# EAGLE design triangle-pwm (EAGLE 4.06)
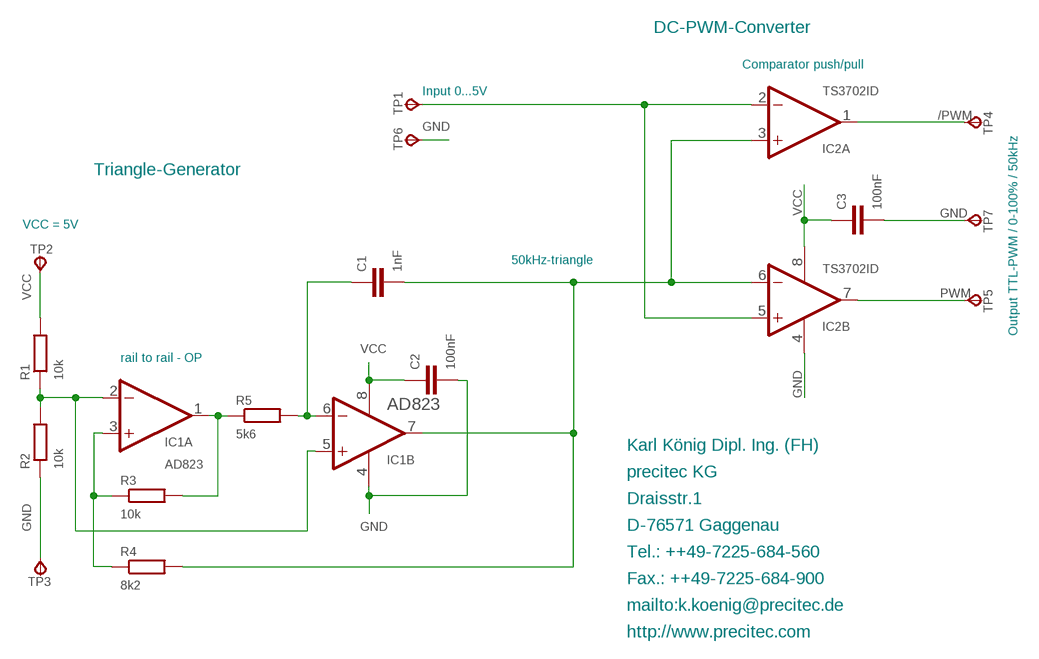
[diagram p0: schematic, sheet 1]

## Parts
C1  1nF  C-EUC1206  [C1206]
C2  100nF  C-EUC1206  [C1206]
C3  100nF  C-EUC1206  [C1206]
IC1  AD823  2AMP_P8+4D  [SO08]
IC2  TS3702ID  2AMP_P8+4D  [SO08]
R1  10k  R-EU_R1206  [R1206]
R2  10k  R-EU_R1206  [R1206]
R3  10k  R-EU_R1206  [R1206]
R4  8k2  R-EU_R1206  [R1206]
R5  5k6  R-EU_R1206  [R1206]
TP1  TP20R  [TP20R]
TP2  TP20R  [TP20R]
TP3  TP20R  [TP20R]
TP4  TP20R  [TP20R]
TP5  TP20R  [TP20R]
TP6  TP20R  [TP20R]
TP7  TP20R  [TP20R]

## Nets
/PWM: IC2.1(A:OUT) TP4.TP
GND: C2.2 C3.2 IC1.4(P:V-) IC2.4(P:V-) R2.1 TP3.TP TP6.TP TP7.TP
N$1: IC1.2(A:-IN) IC1.5(B:+IN) R1.1 R2.2
N$2: IC1.3(A:+IN) R3.1 R4.1
N$3: IC1.1(A:OUT) R3.2 R5.1
N$4: C1.1 IC1.6(B:-IN) R5.2
N$5: C1.2 IC1.7(B:OUT) IC2.3(A:+IN) IC2.6(B:-IN) R4.2
N$6: IC2.2(A:-IN) IC2.5(B:+IN) TP1.TP
PWM: IC2.7(B:OUT) TP5.TP
VCC: C2.1 C3.1 IC1.8(P:V+) IC2.8(P:V+) R1.2 TP2.TP

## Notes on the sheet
- DC-PWM-Converter
- Comparator push/pull
- Input 0...5V
- Triangle-Generator
- VCC = 5V
- 50kHz-triangle
- Output TTL-PWM / 0-100% / 50kHz
- rail to rail - OP
- Karl König Dipl. Ing. (FH)
- precitec KG
- Draisstr.1
- D-76571 Gaggenau
- Tel.: ++49-7225-684-560
- Fax.: ++49-7225-684-900
- mailto:k.koenig@precitec.de
- http://www.precitec.com

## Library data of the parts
C1-C3 = rcl:C-EU: CAPACITOR, European symbol
IC1 IC2 = linear:2AMP_P8+4: OP AMP
R1-R5 = rcl:R-EU_: RESISTOR, European symbol
TP1-TP7 = testpad:TP20R: TEST PIN

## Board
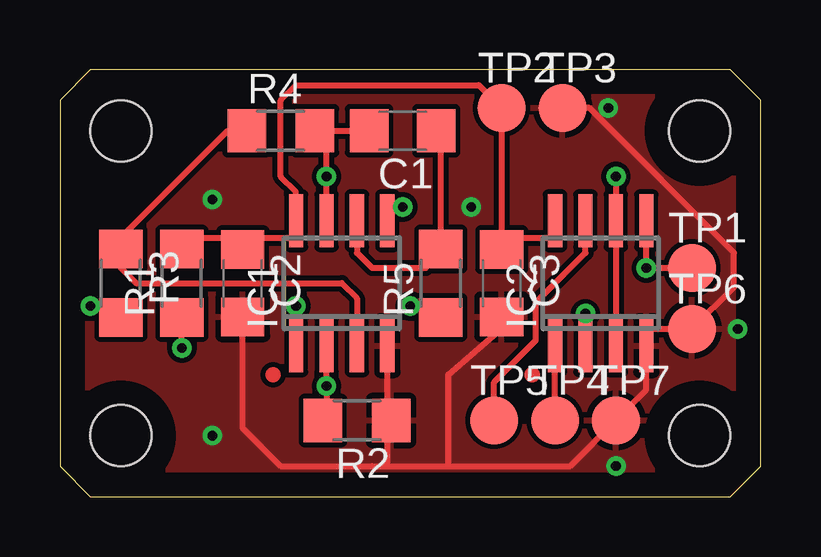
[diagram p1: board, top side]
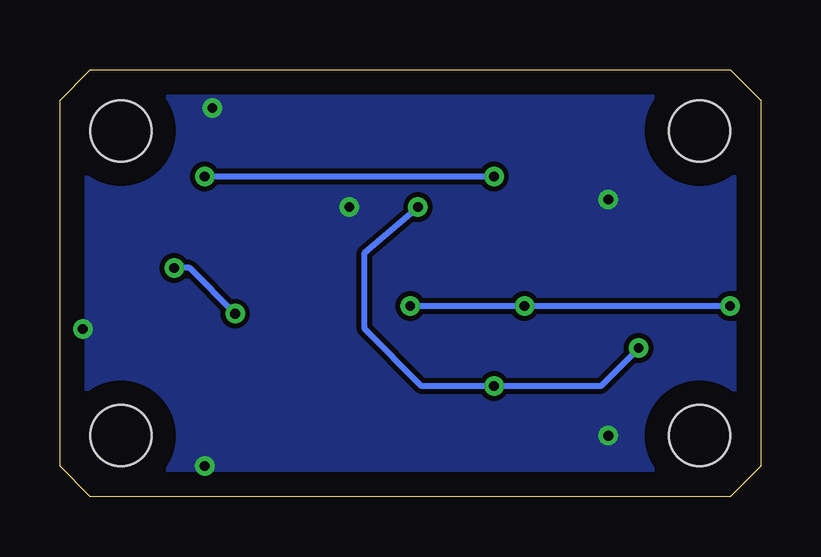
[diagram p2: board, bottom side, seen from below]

Size 29.21 x 17.78 mm. Coordinates in mm from the lower left corner, seen from the top.
Outline: 1.27,0 27.94,0 29.21,1.27 29.21,16.51 27.94,17.78 1.27,17.78 0,16.51 0,1.27 1.27,0
Copper layers used: Top, Bottom
Holes 2.54 mm at 2.54,2.54 2.54,15.24 26.67,15.24 26.67,2.54
tRestrict: area 0.3,13 to 4.8,17.5; area 0.3,0.3 to 4.8,4.8; area 24.4,0.3 to 28.9,4.8; area 24.4,13 to 28.9,17.5
bRestrict: area 0.3,13 to 4.8,17.5; area 24.4,0.3 to 28.9,4.8; area 0.3,0.3 to 4.8,4.8; area 24.4,13 to 28.9,17.5

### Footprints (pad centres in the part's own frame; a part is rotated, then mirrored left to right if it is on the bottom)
C1206 = smd 1.6 x 1.8: 1 -1.4,0; 2 1.4,0
SO08 = smd 0.6 x 2.2: 1 -1.905,-2.6; 2 -0.635,-2.6; 3 0.635,-2.6; 4 1.905,-2.6; 5 1.905,2.6; 6 0.635,2.6; 7 -0.635,2.6; 8 -1.905,2.6
R1206 = smd 1.6 x 1.803: 1 -1.422,0; 2 1.422,0
TP20R = smd 2 x 2: TP 0,0

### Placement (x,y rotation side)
C1  14.29,15.24 180 top
C2  7.62,8.89 270 top
C3  18.41,8.89 270 top
IC1  11.75,8.89 0 top
IC2  22.54,8.89 0 top
R1  5.08,8.89 90 top
R2  12.38,3.17 180 top
R3  2.54,8.89 270 top
R4  9.21,15.24 0 top
R5  15.88,8.89 90 top
TP1  26.35,9.53 0 top
TP2  18.41,16.19 0 top
TP3  20.95,16.19 0 top
TP4  20.64,3.17 0 top
TP5  18.1,3.17 0 top
TP6  26.35,6.99 0 top
TP7  23.18,3.17 0 top

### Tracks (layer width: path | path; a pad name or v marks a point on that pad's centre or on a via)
/PWM
  Top 0.254: TP4.TP IC2.1
GND  (via drill 0.41 pad 0.81)
  Top 0.254: R2.1 13.65,3.33 | 13.65,3.33 IC1.4 | 13.02,1.27 9.21,1.27 7.62,2.86 C2.2 | 16.19,1.27 16.19,5.08 18.41,6.99 C3.2 | 16.19,1.27 21.27,1.27 TP7.TP 24.45,4.45 IC2.4 24.45,6.99 TP6.TP 28.1,8.73 28.1,10.16 22.07,16.19 TP3.TP | 13.65,3.33 13.65,1.27 13.02,1.27 | 13.02,1.27 16.19,1.27
  other vias: 6.35,12.38 6.35,2.54 28.26,6.99 22.86,16.19 23.18,1.27 17.14,12.06
  pour Top: 0.32,16.19 0.32,1.59 1.59,0.32 27.62,0.32 28.89,1.59 28.89,16.19 27.62,17.46 1.59,17.46
  pour Bottom: 0.32,16.19 0.32,1.59 1.59,0.32 27.62,0.32 28.89,1.59 28.89,16.19 27.62,17.46 1.59,17.46
N$1  (via drill 0.41 pad 0.81)
  Top 0.254: R2.2 11.11,3.17 v11.11,4.6 | IC1.2 11.11,6.35 | v11.11,4.6 IC1.2 | v5.08,6.19 R1.1 | v11.11,4.6 IC1.2 | IC1.5 13.65,12.06 v14.29,12.06
  Bottom 0.254: v5.08,6.19 6.67,4.6 v11.11,4.6 14.13,4.6 16.51,6.99 16.51,10.16 v14.29,12.06
N$2
  Top 0.254: IC1.3 12.38,8.26 11.75,8.89 3.17,8.89 2.54,9.53 R3.1 2.54,10.79 6.99,15.24 R4.1
N$3  (via drill 0.41 pad 0.81)
  Top 0.254: R3.2 2.06,7.94 v1.27,7.94 | v9.84,7.94 IC1.1 | R5.1 15.4,7.94 v14.61,7.94
  Bottom 0.254: v1.27,7.94 v9.84,7.94 v14.61,7.94
N$4
  Top 0.254: C1.1 15.88,15.24 R5.2 15.88,10.16 15.24,9.53 13.02,9.53 12.38,10.16 IC1.6
N$5  (via drill 0.41 pad 0.81)
  Top 0.254: 11.11,15.24 v11.11,13.34 IC1.7 | 11.11,15.24 R4.2 | 11.11,15.24 C1.2 | IC2.3 IC2.6 v23.18,13.34
  Bottom 0.254: v11.11,13.34 v23.18,13.34
N$6  (via drill 0.41 pad 0.81)
  Top 0.254: IC2.5 v24.45,9.53 TP1.TP | IC2.2 v21.91,7.62
  Bottom 0.254: v24.45,9.53 23.81,9.53 v21.91,7.62
PWM
  Top 0.254: TP5.TP 18.1,4.76 19.68,6.35 19.84,6.51 19.84,8.1 21.91,10.16 IC2.7
VCC
  Top 0.254: R1.2 5.71,10.79 6.99,10.79 C2.1 7.62,10.79 9.84,10.79 9.84,11.43 | C3.1 19.05,10.79 20.64,10.79 IC2.8 | C3.1 18.41,10.16 | C3.1 TP2.TP 17.46,17.14 9.84,17.14 9.21,16.51 9.21,13.34 9.84,12.7 9.84,11.43 | 9.84,11.43 IC1.8
(copper drawn outside any net)
  shapes: Top circle x2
